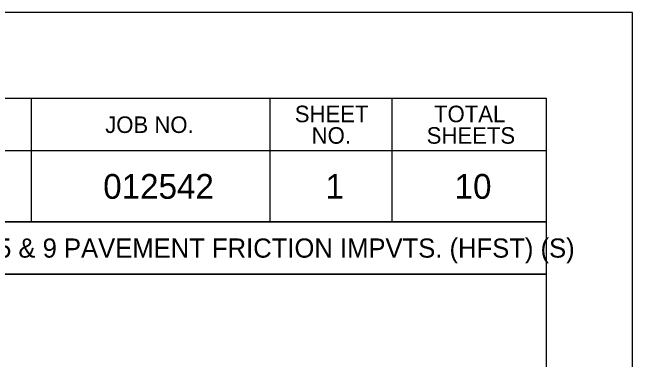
# Model space of a CAD drawing. Extents: x -819161 to 80911, y -6604 to 768454.
# Drawn here: x 50478 to 52278, y 9653 to 10660 of the extents above; entities that cross this region are included whole.
import ezdxf

# ---------------------------------------------------------------- set-up
doc = ezdxf.new("R2010")
doc.units = 0
for name, color, linetype in [('Default', 7, 'Continuous'), ('DSN_DRFT_Junk-No-Plot', 7, 'Continuous'), ('SHET_Annotations', 7, 'Continuous'), ('SHET_Border-Lines', 7, 'Continuous'), ('SHET_Border-Text', 7, 'Continuous'), ('SHET_Stamp-Prelim', 7, 'Continuous')]:
    doc.layers.add(name, color=color, linetype=linetype)

msp = doc.modelspace()

# ---------------------------------------------------------------- linework, layer by layer
at = {"layer": 'Default'}
msp.add_lwpolyline([(35278.1, 10659.9), (35278.1, -340.1), (52278.1, -340.1), (52278.1, 10659.9)], close=True, dxfattribs=at)
at = {"layer": 'DSN_DRFT_Junk-No-Plot'}
msp.add_lwpolyline([(35278.1, -340.1), (52278.1, -340.1), (52278.1, 10659.9), (35278.1, 10659.9)], close=True, dxfattribs=at)
at = {"layer": 'SHET_Border-Lines'}
for p, q in [((50532.8, 10409.9), (50532.8, 10052)), ((51225.4, 10409.9), (51225.4, 10052)), ((51579.3, 10409.9), (51579.3, 10052)), ((52028.1, 10258.3), (49830, 10258.3)), ((52028.1, 10259.3), (52028.1, 10259.3)), ((52028.1, 10052), (49830, 10052)), ((49981, 10052), (52028.1, 10052)), ((52028.1, 9900.4), (48833.5, 9900.4))]:
    msp.add_line(p, q, dxfattribs=at)
for points in [[(35528.1, -90.1), (52028.1, -90.1), (52028.1, 10409.9), (35528.1, 10409.9)], [(35528.1, -90.1), (52028.1, -90.1), (52028.1, 10409.9), (35528.1, 10409.9)], [(48833.5, 9900.4), (52028.1, 9900.4), (52028.1, 10409.9), (48833.5, 10409.9)]]:
    msp.add_lwpolyline(points, close=True, dxfattribs=at)
at = {"layer": 'SHET_Stamp-Prelim'}
msp.add_lwpolyline([(50928.2, 9900), (50930, 9900), (50930, 9900.4), (50928.2, 9900.4)], close=True, dxfattribs=at)

# ---------------------------------------------------------------- texts
at = {"layer": 'SHET_Annotations'}
for s, height, p in [('012542', 72, (50741.5, 10119.1)), ('1', 72, (51386.7, 10119.1)), ('10', 72, (51761.5, 10119.1)), ('DISTRICTS 5 & 9 PAVEMENT FRICTION IMPVTS. (HFST) (S)', 55.578, (50020.6, 9948.4))]:
    msp.add_text(s, height=height, dxfattribs=at).set_placement(p)
at = {"layer": 'SHET_Border-Text'}
for s, p in [('SHEET', (51297.6, 10341.3)), ('TOTAL', (51701.7, 10341.3)), ('JOB NO.', (50747.3, 10310.1)), ('NO.', (51346.5, 10278.9)), ('SHEETS', (51680.3, 10278.9))]:
    msp.add_text(s, height=48, dxfattribs=at).set_placement(p)
at = {"layer": 'SHET_Stamp-Prelim'}
for s, height, p in [('PRELIMINARY', 0.13, (50928.3, 9900.2)), ('SUBJECT TO REVISION', 0.09, (50928.4, 9900.1))]:
    msp.add_text(s, height=height, dxfattribs=at).set_placement(p)

doc.saveas('drawing.dxf')
